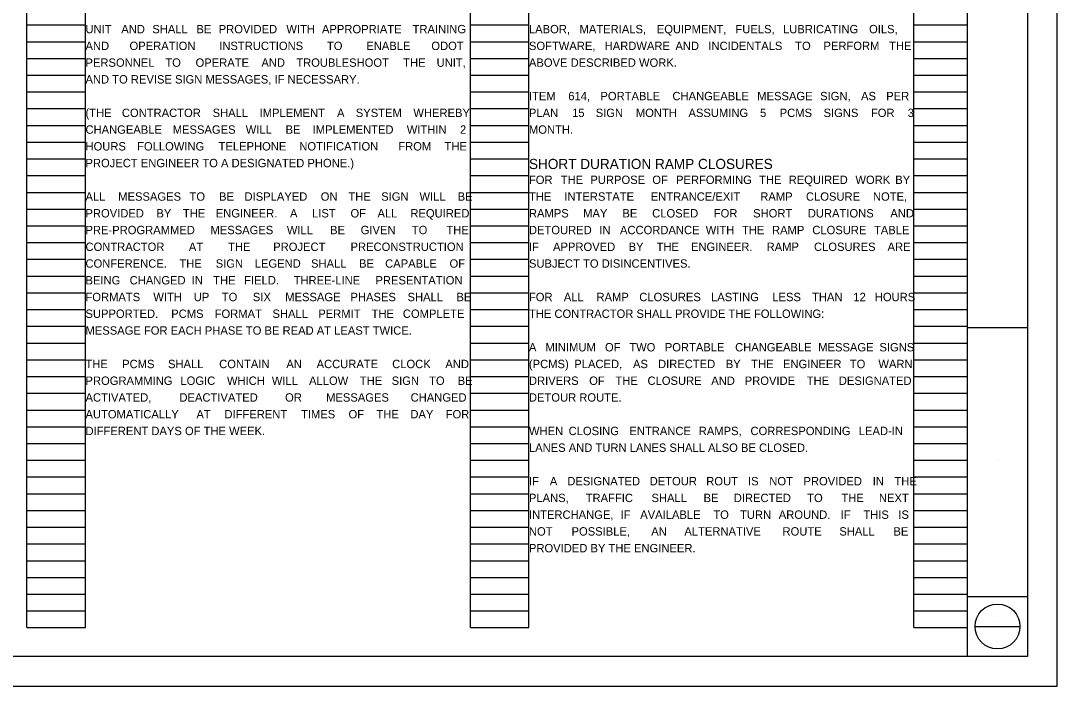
# Model space of a CAD drawing. Extents: x 0 to 34, y 0 to 22.
# Drawn here: x 16.66 to 34, y 0 to 11.13 of the extents above; entities that cross this region are included whole.
import ezdxf

# ---------------------------------------------------------------- set-up
doc = ezdxf.new("R2010")
doc.units = 0
for name, color, linetype in [('BD_P_Text', 7, 'Continuous'), ('SH_Border', 7, 'Continuous'), ('SH_Cut_Line', 7, 'Continuous'), ('SH_Data', 7, 'Continuous')]:
    doc.layers.add(name, color=color, linetype=linetype)

msp = doc.modelspace()

# ---------------------------------------------------------------- linework, layer by layer
at = {"layer": 'SH_Border'}
for p, q in [((32.5, 0.5), (32.5, 21.5)), ((32.5, 6), (33.5, 6)), ((32.5, 1.5), (33.5, 1.5))]:
    msp.add_line(p, q, dxfattribs=at)
msp.add_lwpolyline([(2, 21.5), (33.5, 21.5), (33.5, 0.5), (2, 0.5)], close=True, dxfattribs=at)
at = {"layer": 'SH_Cut_Line'}
msp.add_lwpolyline([(0, 0), (34, 0), (34, 22), (0, 22)], close=True, dxfattribs=at)
at = {"layer": 'SH_Data'}
for p, q in [((16.76, 0.98), (16.76, 21.14)), ((17.74, 0.98), (17.74, 21.14)), ((24.18, 0.98), (24.18, 21.14)), ((25.16, 0.98), (25.16, 21.14)), ((31.6, 0.98), (31.6, 21.14)), ((32.5, 0.98), (32.5, 21.14)), ((16.76, 11.06), (17.74, 11.06)), ((24.18, 11.06), (25.16, 11.06)), ((31.6, 11.06), (32.5, 11.06)), ((16.76, 10.78), (17.74, 10.78)), ((24.18, 10.78), (25.16, 10.78)), ((31.6, 10.78), (32.5, 10.78)), ((16.76, 10.5), (17.74, 10.5)), ((24.18, 10.5), (25.16, 10.5)), ((31.6, 10.5), (32.5, 10.5)), ((16.76, 10.22), (17.74, 10.22)), ((24.18, 10.22), (25.16, 10.22)), ((31.6, 10.22), (32.5, 10.22)), ((16.76, 9.94), (17.74, 9.94)), ((24.18, 9.94), (25.16, 9.94)), ((31.6, 9.94), (32.5, 9.94)), ((16.76, 9.66), (17.74, 9.66)), ((24.18, 9.66), (25.16, 9.66)), ((31.6, 9.66), (32.5, 9.66)), ((16.76, 9.38), (17.74, 9.38)), ((24.18, 9.38), (25.16, 9.38)), ((31.6, 9.38), (32.5, 9.38)), ((16.76, 9.1), (17.74, 9.1)), ((24.18, 9.1), (25.16, 9.1)), ((31.6, 9.1), (32.5, 9.1)), ((16.76, 8.82), (17.74, 8.82)), ((24.18, 8.82), (25.16, 8.82)), ((31.6, 8.82), (32.5, 8.82)), ((16.76, 8.54), (17.74, 8.54)), ((24.18, 8.54), (25.16, 8.54)), ((31.6, 8.54), (32.5, 8.54)), ((16.76, 8.26), (17.74, 8.26)), ((24.18, 8.26), (25.16, 8.26)), ((31.6, 8.26), (32.5, 8.26)), ((16.76, 7.98), (17.74, 7.98)), ((24.18, 7.98), (25.16, 7.98)), ((31.6, 7.98), (32.5, 7.98)), ((16.76, 7.7), (17.74, 7.7)), ((24.18, 7.7), (25.16, 7.7)), ((31.6, 7.7), (32.5, 7.7)), ((16.76, 7.42), (17.74, 7.42)), ((24.18, 7.42), (25.16, 7.42)), ((31.6, 7.42), (32.5, 7.42)), ((16.76, 7.14), (17.74, 7.14)), ((24.18, 7.14), (25.16, 7.14)), ((31.6, 7.14), (32.5, 7.14)), ((16.76, 6.86), (17.74, 6.86)), ((24.18, 6.86), (25.16, 6.86)), ((31.6, 6.86), (32.5, 6.86)), ((16.76, 6.58), (17.74, 6.58)), ((24.18, 6.58), (25.16, 6.58)), ((31.6, 6.58), (32.5, 6.58)), ((16.76, 6.3), (17.74, 6.3)), ((24.18, 6.3), (25.16, 6.3)), ((31.6, 6.3), (32.5, 6.3)), ((16.76, 6.02), (17.74, 6.02)), ((24.18, 6.02), (25.16, 6.02)), ((31.6, 6.02), (32.5, 6.02)), ((16.76, 5.74), (17.74, 5.74)), ((24.18, 5.74), (25.16, 5.74)), ((31.6, 5.74), (32.5, 5.74)), ((16.76, 5.46), (17.74, 5.46)), ((24.18, 5.46), (25.16, 5.46)), ((31.6, 5.46), (32.5, 5.46)), ((16.76, 5.18), (17.74, 5.18)), ((24.18, 5.18), (25.16, 5.18)), ((31.6, 5.18), (32.5, 5.18)), ((16.76, 4.9), (17.74, 4.9)), ((24.18, 4.9), (25.16, 4.9)), ((31.6, 4.9), (32.5, 4.9)), ((16.76, 4.62), (17.74, 4.62)), ((24.18, 4.62), (25.16, 4.62)), ((31.6, 4.62), (32.5, 4.62)), ((16.76, 4.34), (17.74, 4.34)), ((24.18, 4.34), (25.16, 4.34)), ((31.6, 4.34), (32.5, 4.34)), ((16.76, 4.06), (17.74, 4.06)), ((24.18, 4.06), (25.16, 4.06)), ((31.6, 4.06), (32.5, 4.06)), ((16.76, 3.78), (17.74, 3.78)), ((24.18, 3.78), (25.16, 3.78)), ((31.6, 3.78), (32.5, 3.78)), ((33, 3.792), (33, 3.792)), ((16.76, 3.5), (17.74, 3.5)), ((24.18, 3.5), (25.16, 3.5)), ((31.6, 3.5), (32.5, 3.5)), ((16.76, 3.22), (17.74, 3.22)), ((24.18, 3.22), (25.16, 3.22)), ((31.6, 3.22), (32.5, 3.22)), ((16.76, 2.94), (17.74, 2.94)), ((24.18, 2.94), (25.16, 2.94)), ((31.6, 2.94), (32.5, 2.94)), ((16.76, 2.66), (17.74, 2.66)), ((24.18, 2.66), (25.16, 2.66)), ((31.6, 2.66), (32.5, 2.66)), ((16.76, 2.38), (17.74, 2.38)), ((24.18, 2.38), (25.16, 2.38)), ((31.6, 2.38), (32.5, 2.38)), ((16.76, 2.1), (17.74, 2.1)), ((24.18, 2.1), (25.16, 2.1)), ((31.6, 2.1), (32.5, 2.1)), ((16.76, 1.82), (17.74, 1.82)), ((24.18, 1.82), (25.16, 1.82)), ((31.6, 1.82), (32.5, 1.82)), ((16.76, 1.54), (17.74, 1.54)), ((24.18, 1.54), (25.16, 1.54)), ((31.6, 1.54), (32.5, 1.54)), ((16.76, 1.26), (17.74, 1.26)), ((24.18, 1.26), (25.16, 1.26)), ((31.6, 1.26), (32.5, 1.26)), ((33, 1.085), (33, 1.085)), ((16.76, 0.98), (17.74, 0.98)), ((24.18, 0.98), (25.16, 0.98)), ((31.6, 0.98), (32.5, 0.98)), ((32.625, 1), (33.375, 1)), ((33, 0.745), (33, 0.745))]:
    msp.add_line(p, q, dxfattribs=at)
msp.add_circle((33, 1), 0.375, dxfattribs=at)

# ---------------------------------------------------------------- texts
at = {"layer": 'BD_P_Text'}
for s, height, p in [('UNIT ', 0.14, (17.74, 10.92)), ('AND ', 0.14, (18.339, 10.92)), ('SHALL ', 0.14, (18.858, 10.92)), ('BE ', 0.14, (19.596, 10.92)), ('PROVIDED ', 0.14, (19.969, 10.92)), ('WITH ', 0.14, (21.101, 10.92)), ('APPROPRIATE ', 0.14, (21.697, 10.92)), ('TRAINING ', 0.14, (23.213, 10.92)), ('LABOR, ', 0.14, (25.16, 10.92)), ('MATERIALS, ', 0.14, (26.007, 10.92)), ('EQUIPMENT, ', 0.14, (27.299, 10.92)), ('FUELS, ', 0.14, (28.615, 10.92)), ('LUBRICATING ', 0.14, (29.411, 10.92)), ('OILS, ', 0.14, (30.851, 10.92)), ('AND ', 0.14, (17.74, 10.64)), ('OPERATION ', 0.14, (18.477, 10.64)), ('INSTRUCTIONS ', 0.14, (19.978, 10.64)), ('TO ', 0.14, (21.78, 10.64)), ('ENABLE ', 0.14, (22.438, 10.64)), ('ODOT ', 0.14, (23.527, 10.64)), ('SOFTWARE, ', 0.14, (25.16, 10.64)), ('HARDWARE ', 0.14, (26.427, 10.64)), ('AND ', 0.14, (27.611, 10.64)), ('INCIDENTALS ', 0.14, (28.162, 10.64)), ('TO ', 0.14, (29.615, 10.64)), ('PERFORM ', 0.14, (30.088, 10.64)), ('THE ', 0.14, (31.186, 10.64)), ('PERSONNEL ', 0.14, (17.74, 10.36)), ('TO ', 0.14, (19.076, 10.36)), ('OPERATE ', 0.14, (19.582, 10.36)), ('AND ', 0.14, (20.684, 10.36)), ('TROUBLESHOOT ', 0.14, (21.267, 10.36)), ('THE ', 0.14, (23.056, 10.36)), ('UNIT, ', 0.14, (23.615, 10.36)), ('ABOVE DESCRIBED WORK.', 0.14, (25.16, 10.36)), ('AND TO REVISE SIGN MESSAGES, IF NECESSARY.', 0.14, (17.74, 10.08)), ('ITEM ', 0.14, (25.16, 9.8)), ('614, ', 0.14, (25.818, 9.8)), ('PORTABLE ', 0.14, (26.356, 9.8)), ('CHANGEABLE ', 0.14, (27.561, 9.8)), ('MESSAGE ', 0.14, (28.98, 9.8)), ('SIGN, ', 0.14, (30.032, 9.8)), ('AS ', 0.14, (30.717, 9.8)), ('PER ', 0.14, (31.138, 9.8)), ('(THE ', 0.14, (17.74, 9.52)), ('CONTRACTOR ', 0.14, (18.349, 9.52)), ('SHALL ', 0.14, (19.867, 9.52)), ('IMPLEMENT ', 0.14, (20.654, 9.52)), ('A ', 0.14, (21.949, 9.52)), ('SYSTEM ', 0.14, (22.263, 9.52)), ('WHEREBY ', 0.14, (23.226, 9.52)), ('PLAN ', 0.14, (25.16, 9.52)), ('15 ', 0.14, (25.882, 9.52)), ('SIGN ', 0.14, (26.277, 9.52)), ('MONTH ', 0.14, (26.949, 9.52)), ('ASSUMING ', 0.14, (27.829, 9.52)), ('5 ', 0.14, (29.027, 9.52)), ('PCMS ', 0.14, (29.356, 9.52)), ('SIGNS ', 0.14, (30.09, 9.52)), ('FOR ', 0.14, (30.882, 9.52)), ('3 ', 0.14, (31.498, 9.52)), ('CHANGEABLE ', 0.14, (17.74, 9.24)), ('MESSAGES ', 0.14, (19.2, 9.24)), ('WILL ', 0.14, (20.421, 9.24)), ('BE ', 0.14, (21.088, 9.24)), ('IMPLEMENTED ', 0.14, (21.541, 9.24)), ('WITHIN ', 0.14, (23.116, 9.24)), ('2 ', 0.14, (24.006, 9.24)), ('MONTH.', 0.14, (25.16, 9.24)), ('HOURS ', 0.14, (17.74, 8.96)), ('FOLLOWING ', 0.14, (18.604, 8.96)), ('TELEPHONE ', 0.14, (19.967, 8.96)), ('NOTIFICATION ', 0.14, (21.318, 8.96)), ('FROM ', 0.14, (22.974, 8.96)), ('THE ', 0.14, (23.748, 8.96)), ('PROJECT ENGINEER TO A DESIGNATED PHONE.)', 0.14, (17.74, 8.68)), ('SHORT DURATION RAMP CLOSURES', 0.17, (25.16, 8.65)), ('FOR ', 0.14, (25.16, 8.4)), ('THE ', 0.14, (25.693, 8.4)), ('PURPOSE ', 0.14, (26.188, 8.4)), ('OF ', 0.14, (27.224, 8.4)), ('PERFORMING ', 0.14, (27.621, 8.4)), ('THE ', 0.14, (29.011, 8.4)), ('REQUIRED ', 0.14, (29.506, 8.4)), ('WORK ', 0.14, (30.623, 8.4)), ('BY ', 0.14, (31.289, 8.4)), ('ALL ', 0.14, (17.74, 8.12)), ('MESSAGES ', 0.14, (18.288, 8.12)), ('TO ', 0.14, (19.481, 8.12)), ('BE ', 0.14, (19.975, 8.12)), ('DISPLAYED ', 0.14, (20.401, 8.12)), ('ON ', 0.14, (21.676, 8.12)), ('THE ', 0.14, (22.139, 8.12)), ('SIGN ', 0.14, (22.688, 8.12)), ('WILL ', 0.14, (23.329, 8.12)), ('BE ', 0.14, (23.968, 8.12)), ('THE ', 0.14, (25.16, 8.12)), ('INTERSTATE ', 0.14, (25.753, 8.12)), ('ENTRANCE/EXIT ', 0.14, (27.198, 8.12)), ('RAMP ', 0.14, (29.031, 8.12)), ('CLOSURE ', 0.14, (29.795, 8.12)), ('NOTE, ', 0.14, (30.916, 8.12)), ('PROVIDED ', 0.14, (17.74, 7.84)), ('BY ', 0.14, (18.927, 7.84)), ('THE ', 0.14, (19.37, 7.84)), ('ENGINEER. ', 0.14, (19.92, 7.84)), (' A ', 0.14, (21.11, 7.84)), ('LIST ', 0.14, (21.531, 7.84)), ('OF ', 0.14, (22.174, 7.84)), ('ALL ', 0.14, (22.626, 7.84)), ('REQUIRED ', 0.14, (23.176, 7.84)), ('RAMPS ', 0.14, (25.16, 7.84)), ('MAY ', 0.14, (26.067, 7.84)), ('BE ', 0.14, (26.724, 7.84)), ('CLOSED ', 0.14, (27.222, 7.84)), ('FOR ', 0.14, (28.253, 7.84)), ('SHORT ', 0.14, (28.911, 7.84)), ('DURATIONS ', 0.14, (29.826, 7.84)), ('AND ', 0.14, (31.207, 7.84)), ('PRE-PROGRAMMED ', 0.14, (17.74, 7.56)), ('MESSAGES ', 0.14, (19.831, 7.56)), ('WILL ', 0.14, (21.109, 7.56)), ('BE ', 0.14, (21.833, 7.56)), ('GIVEN ', 0.14, (22.345, 7.56)), ('TO ', 0.14, (23.2, 7.56)), ('THE ', 0.14, (23.779, 7.56)), ('DETOURED ', 0.14, (25.16, 7.56)), ('IN ', 0.14, (26.338, 7.56)), ('ACCORDANCE ', 0.14, (26.683, 7.56)), ('WITH ', 0.14, (28.118, 7.56)), ('THE ', 0.14, (28.724, 7.56)), ('RAMP ', 0.14, (29.227, 7.56)), ('CLOSURE ', 0.14, (29.901, 7.56)), ('TABLE ', 0.14, (30.933, 7.56)), ('CONTRACTOR ', 0.14, (17.74, 7.28)), ('AT ', 0.14, (19.469, 7.28)), ('THE ', 0.14, (20.126, 7.28)), ('PROJECT ', 0.14, (20.881, 7.28)), ('PRECONSTRUCTION ', 0.14, (22.175, 7.28)), ('IF ', 0.14, (25.16, 7.28)), ('APPROVED ', 0.14, (25.563, 7.28)), ('BY ', 0.14, (26.828, 7.28)), ('THE ', 0.14, (27.296, 7.28)), ('ENGINEER. ', 0.14, (27.871, 7.28)), (' RAMP ', 0.14, (29.085, 7.28)), ('CLOSURES ', 0.14, (29.93, 7.28)), ('ARE ', 0.14, (31.16, 7.28)), ('CONFERENCE. ', 0.14, (17.74, 7)), (' THE ', 0.14, (19.259, 7)), ('SIGN ', 0.14, (19.919, 7)), ('LEGEND ', 0.14, (20.572, 7)), ('SHALL ', 0.14, (21.514, 7)), ('BE ', 0.14, (22.317, 7)), ('CAPABLE ', 0.14, (22.754, 7)), ('OF ', 0.14, (23.831, 7)), ('SUBJECT TO DISINCENTIVES.', 0.14, (25.16, 7)), ('BEING ', 0.14, (17.74, 6.72)), ('CHANGED ', 0.14, (18.479, 6.72)), ('IN ', 0.14, (19.518, 6.72)), ('THE ', 0.14, (19.877, 6.72)), ('FIELD. ', 0.14, (20.395, 6.72)), (' THREE-LINE ', 0.14, (21.171, 6.72)), ('PRESENTATION ', 0.14, (22.592, 6.72)), ('FORMATS ', 0.14, (17.74, 6.44)), ('WITH ', 0.14, (18.875, 6.44)), ('UP ', 0.14, (19.551, 6.44)), ('TO ', 0.14, (20.021, 6.44)), ('SIX ', 0.14, (20.541, 6.44)), ('MESSAGE ', 0.14, (21.082, 6.44)), ('PHASES ', 0.14, (22.174, 6.44)), ('SHALL ', 0.14, (23.129, 6.44)), ('BE ', 0.14, (23.947, 6.44)), ('FOR ', 0.14, (25.16, 6.44)), ('ALL ', 0.14, (25.744, 6.44)), ('RAMP ', 0.14, (26.29, 6.44)), ('CLOSURES ', 0.14, (27.006, 6.44)), ('LASTING ', 0.14, (28.207, 6.44)), ('LESS ', 0.14, (29.232, 6.44)), ('THAN ', 0.14, (29.897, 6.44)), ('12 ', 0.14, (30.588, 6.44)), ('HOURS ', 0.14, (30.947, 6.44)), ('SUPPORTED. ', 0.14, (17.74, 6.16)), (' PCMS ', 0.14, (19.123, 6.16)), ('FORMAT ', 0.14, (19.901, 6.16)), ('SHALL ', 0.14, (20.869, 6.16)), ('PERMIT ', 0.14, (21.635, 6.16)), ('THE ', 0.14, (22.527, 6.16)), ('COMPLETE ', 0.14, (23.05, 6.16)), ('THE CONTRACTOR SHALL PROVIDE THE FOLLOWING:', 0.14, (25.16, 6.16)), ('MESSAGE FOR EACH PHASE TO BE READ AT LEAST TWICE.', 0.14, (17.74, 5.88)), ('A ', 0.14, (25.16, 5.6)), ('MINIMUM ', 0.14, (25.436, 5.6)), ('OF ', 0.14, (26.432, 5.6)), ('TWO ', 0.14, (26.839, 5.6)), ('PORTABLE ', 0.14, (27.433, 5.6)), ('CHANGEABLE ', 0.14, (28.61, 5.6)), ('MESSAGE ', 0.14, (30, 5.6)), ('SIGNS ', 0.14, (31.024, 5.6)), ('THE ', 0.14, (17.74, 5.32)), ('PCMS ', 0.14, (18.353, 5.32)), ('SHALL ', 0.14, (19.121, 5.32)), ('CONTAIN ', 0.14, (19.977, 5.32)), ('AN ', 0.14, (21.101, 5.32)), ('ACCURATE ', 0.14, (21.607, 5.32)), ('CLOCK ', 0.14, (22.872, 5.32)), ('AND ', 0.14, (23.761, 5.32)), ('(PCMS) ', 0.14, (25.16, 5.32)), ('PLACED, ', 0.14, (25.919, 5.32)), ('AS ', 0.14, (26.901, 5.32)), ('DIRECTED ', 0.14, (27.32, 5.32)), ('BY ', 0.14, (28.454, 5.32)), ('THE ', 0.14, (28.879, 5.32)), ('ENGINEER ', 0.14, (29.411, 5.32)), ('TO ', 0.14, (30.529, 5.32)), ('WARN ', 0.14, (31.007, 5.32)), ('PROGRAMMING ', 0.14, (17.74, 5.04)), ('LOGIC ', 0.14, (19.329, 5.04)), ('WHICH ', 0.14, (20.107, 5.04)), ('WILL ', 0.14, (20.858, 5.04)), ('ALLOW ', 0.14, (21.481, 5.04)), ('THE ', 0.14, (22.331, 5.04)), ('SIGN ', 0.14, (22.863, 5.04)), ('TO ', 0.14, (23.489, 5.04)), ('BE ', 0.14, (23.968, 5.04)), ('DRIVERS ', 0.14, (25.16, 5.04)), ('OF ', 0.14, (26.168, 5.04)), ('THE ', 0.14, (26.607, 5.04)), ('CLOSURE ', 0.14, (27.144, 5.04)), ('AND ', 0.14, (28.21, 5.04)), ('PROVIDE ', 0.14, (28.771, 5.04)), ('THE ', 0.14, (29.808, 5.04)), ('DESIGNATED ', 0.14, (30.345, 5.04)), ('ACTIVATED, ', 0.14, (17.74, 4.76)), ('DEACTIVATED ', 0.14, (19.312, 4.76)), ('OR ', 0.14, (21.08, 4.76)), ('MESSAGES ', 0.14, (21.766, 4.76)), ('CHANGED ', 0.14, (23.18, 4.76)), ('DETOUR ROUTE.', 0.14, (25.16, 4.76)), ('AUTOMATICALLY ', 0.14, (17.74, 4.48)), ('AT ', 0.14, (19.596, 4.48)), ('DIFFERENT ', 0.14, (20.065, 4.48)), ('TIMES ', 0.14, (21.346, 4.48)), ('OF ', 0.14, (22.141, 4.48)), ('THE ', 0.14, (22.609, 4.48)), ('DAY ', 0.14, (23.176, 4.48)), ('FOR ', 0.14, (23.767, 4.48)), ('DIFFERENT DAYS OF THE WEEK.', 0.14, (17.74, 4.2)), ('WHEN ', 0.14, (25.16, 4.2)), ('CLOSING ', 0.14, (25.824, 4.2)), ('ENTRANCE ', 0.14, (26.841, 4.2)), ('RAMPS, ', 0.14, (28.001, 4.2)), ('CORRESPONDING ', 0.14, (28.867, 4.2)), ('LEAD-IN ', 0.14, (30.679, 4.2)), ('LANES AND TURN LANES SHALL ALSO BE CLOSED.', 0.14, (25.16, 3.92)), ('IF ', 0.14, (25.16, 3.36)), ('A ', 0.14, (25.51, 3.36)), ('DESIGNATED ', 0.14, (25.802, 3.36)), ('DETOUR ', 0.14, (27.18, 3.36)), ('ROUT ', 0.14, (28.126, 3.36)), ('IS ', 0.14, (28.826, 3.36)), ('NOT ', 0.14, (29.182, 3.36)), ('PROVIDED ', 0.14, (29.754, 3.36)), ('IN ', 0.14, (30.913, 3.36)), ('THE ', 0.14, (31.275, 3.36)), ('PLANS, ', 0.14, (25.16, 3.08)), ('TRAFFIC ', 0.14, (26.11, 3.08)), ('SHALL ', 0.14, (27.211, 3.08)), ('BE ', 0.14, (28.082, 3.08)), ('DIRECTED ', 0.14, (28.587, 3.08)), ('TO ', 0.14, (29.816, 3.08)), ('THE ', 0.14, (30.389, 3.08)), ('NEXT ', 0.14, (31.016, 3.08)), ('INTERCHANGE, ', 0.14, (25.16, 2.8)), ('IF ', 0.14, (26.693, 2.8)), ('AVAILABLE ', 0.14, (27.022, 2.8)), ('TO ', 0.14, (28.245, 2.8)), ('TURN ', 0.14, (28.692, 2.8)), ('AROUND. ', 0.14, (29.34, 2.8)), (' IF ', 0.14, (30.325, 2.8)), ('THIS ', 0.14, (30.755, 2.8)), ('IS ', 0.14, (31.341, 2.8)), ('NOT ', 0.14, (25.16, 2.52)), ('POSSIBLE, ', 0.14, (25.873, 2.52)), ('AN ', 0.14, (27.206, 2.52)), ('ALTERNATIVE ', 0.14, (27.761, 2.52)), ('ROUTE ', 0.14, (29.403, 2.52)), ('SHALL ', 0.14, (30.353, 2.52)), ('BE ', 0.14, (31.259, 2.52)), ('PROVIDED BY THE ENGINEER.', 0.14, (25.16, 2.24))]:
    msp.add_text(s, height=height, dxfattribs=at).set_placement(p)

doc.saveas('drawing.dxf')
